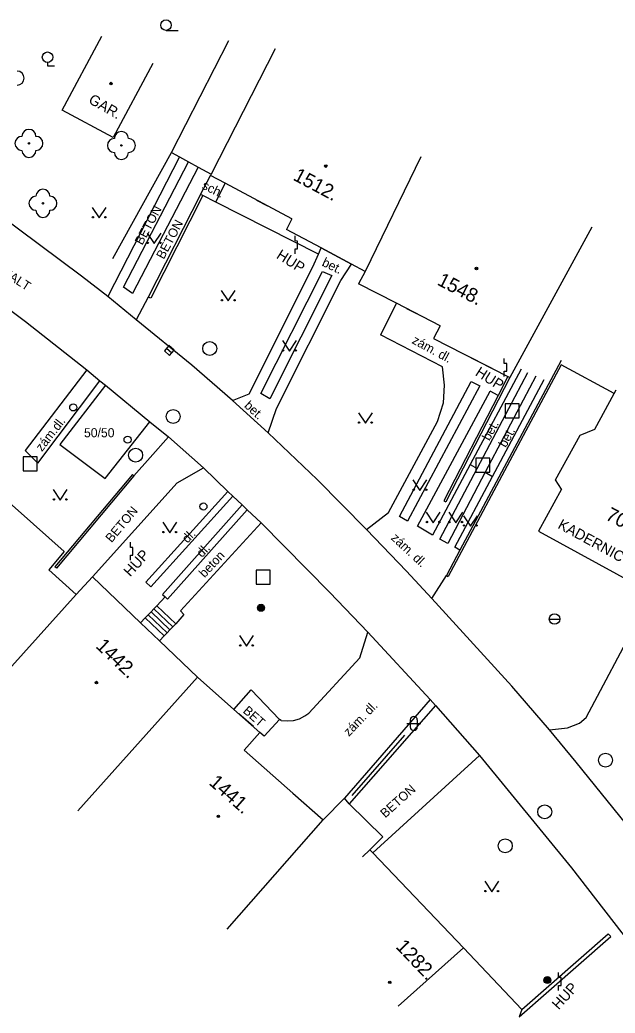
# Model space of a CAD drawing. Extents: x -539244 to -537359, y -1183785 to -1181851.
# Drawn here: x -538380.2 to -538337.7, y -1183558.8 to -1183487.9 of the extents above; entities that cross this region are included whole.
import ezdxf

# ---------------------------------------------------------------- set-up
doc = ezdxf.new("R2010")
doc.units = 0
for name, color, linetype in [('Vrstva 10', 7, 'Continuous'), ('Vrstva 11', 7, 'Continuous'), ('Vrstva 22', 7, 'Continuous'), ('Vrstva 24', 7, 'Continuous'), ('Vrstva 25', 7, 'Continuous'), ('Vrstva 26', 7, 'Continuous'), ('Vrstva 27', 7, 'Continuous'), ('Vrstva 28', 7, 'Continuous'), ('Vrstva 35', 7, 'Continuous'), ('Vrstva 36', 7, 'Continuous'), ('Vrstva 39', 7, 'Continuous'), ('Vrstva 40', 7, 'Continuous'), ('Vrstva 41', 7, 'Continuous'), ('Vrstva 47', 7, 'Continuous'), ('Vrstva 5', 7, 'Continuous'), ('Vrstva 6', 7, 'Continuous'), ('Vrstva 7', 7, 'Continuous'), ('Vrstva 8', 7, 'Continuous')]:
    doc.layers.add(name, color=color, linetype=linetype)

msp = doc.modelspace()

# ---------------------------------------------------------------- linework, layer by layer
at = {"layer": 'Vrstva 10'}
for p, q in [((-538375.8, -1183506.19), (-538382.31, -1183501.34)), ((-538386.84, -1183504.18), (-538379.8, -1183509.42)), ((-538373.93, -1183507.63), (-538375.8, -1183506.19)), ((-538371.9, -1183509.3), (-538373.93, -1183507.63)), ((-538379.8, -1183509.42), (-538375.43, -1183512.88)), ((-538367.92, -1183512.54), (-538371.9, -1183509.3)), ((-538365.03, -1183515.06), (-538367.92, -1183512.54)), ((-538362.48, -1183517.38), (-538365.03, -1183515.06)), ((-538369.59, -1183517.66), (-538367.09, -1183519.86)), ((-538358.99, -1183520.71), (-538362.48, -1183517.38)), ((-538367.09, -1183519.86), (-538365.35, -1183521.57)), ((-538355.45, -1183524.28), (-538358.99, -1183520.71)), ((-538363.98, -1183522.86), (-538362.99, -1183523.8)), ((-538362.99, -1183523.8), (-538358.07, -1183528.76)), ((-538358.07, -1183528.76), (-538355.35, -1183531.61)), ((-538345.09, -1183535.45), (-538350.78, -1183529.2)), ((-538355.35, -1183531.61), (-538350.9, -1183536.41)), ((-538347.39, -1183540.41), (-538340.82, -1183548.43)), ((-538336.46, -1183545.86), (-538340.48, -1183540.88)), ((-538340.82, -1183548.43), (-538334.06, -1183557.17))]:
    msp.add_line(p, q, dxfattribs=at)
for points in [[(-538375.43, -1183512.88), (-538374.49, -1183513.65), (-538374.1, -1183513.98), (-538370.92, -1183516.59), (-538369.59, -1183517.66)], [(-538365.35, -1183521.57), (-538364.99, -1183521.9), (-538364.34, -1183522.52), (-538363.98, -1183522.86)], [(-538350.78, -1183529.2), (-538352.59, -1183527.24), (-538355.45, -1183524.28)], [(-538340.48, -1183540.88), (-538342.38, -1183538.58), (-538345.09, -1183535.45)], [(-538350.9, -1183536.41), (-538350.52, -1183536.83), (-538347.39, -1183540.41)]]:
    msp.add_lwpolyline(points, dxfattribs=at)
at = {"layer": 'Vrstva 11'}
for p, q in [((-538368.8, -1183497.68), (-538373.93, -1183507.63)), ((-538373.58, -1183504.94), (-538369.37, -1183497.36)), ((-538372.82, -1183506.98), (-538368.17, -1183498.03)), ((-538367.47, -1183498.41), (-538372.16, -1183507.43)), ((-538367.32, -1183500.36), (-538366.6, -1183499.01)), ((-538366.223, -1183500.906), (-538365.56, -1183499.56)), ((-538358.88, -1183504.63), (-538358.69, -1183504.17)), ((-538359.29, -1183505.52), (-538358.88, -1183504.63)), ((-538363.84, -1183514.59), (-538359.29, -1183505.52)), ((-538357.3, -1183506.51), (-538356.53, -1183505.33)), ((-538363.01, -1183514.57), (-538358.59, -1183505.86)), ((-538357.94, -1183506.15), (-538362.36, -1183514.95)), ((-538358.59, -1183505.86), (-538357.94, -1183506.15)), ((-538372.16, -1183507.43), (-538372.82, -1183506.98)), ((-538361.88, -1183515.64), (-538357.3, -1183506.51)), ((-538371.04, -1183507.68), (-538371.9, -1183509.3)), ((-538353.306, -1183508.127), (-538354.46, -1183510.37)), ((-538350.02, -1183512.65), (-538354.46, -1183510.37)), ((-538375.43, -1183512.88), (-538379.83, -1183518.63)), ((-538344.42, -1183512.83), (-538348.06, -1183519.64)), ((-538347.55, -1183519.92), (-538343.932, -1183513.077)), ((-538343.361, -1183513.329), (-538346.98, -1183520.19)), ((-538378.93, -1183519.54), (-538374.49, -1183513.65)), ((-538374.1, -1183513.98), (-538377.36, -1183518.2)), ((-538353.11, -1183523.35), (-538347.98, -1183513.7)), ((-538347.37, -1183514.02), (-538352.52, -1183523.67)), ((-538347.98, -1183513.7), (-538347.37, -1183514.02)), ((-538346.46, -1183520.48), (-538342.78, -1183513.56)), ((-538365.03, -1183515.06), (-538363.84, -1183514.59)), ((-538362.36, -1183514.95), (-538363.01, -1183514.57)), ((-538351.81, -1183524.04), (-538346.62, -1183514.4)), ((-538346.052, -1183514.696), (-538346.62, -1183514.4)), ((-538362.48, -1183517.38), (-538361.88, -1183515.64)), ((-538374.13, -1183520.62), (-538370.92, -1183516.59)), ((-538353.89, -1183523.05), (-538350.39, -1183516.56)), ((-538370.9, -1183519.13), (-538369.59, -1183517.66)), ((-538377.36, -1183518.2), (-538374.13, -1183520.62)), ((-538379.83, -1183518.63), (-538378.93, -1183519.54)), ((-538370.9, -1183519.13), (-538372.06, -1183520.45)), ((-538368.97, -1183520.94), (-538367.09, -1183519.86)), ((-538348.06, -1183519.64), (-538350.75, -1183524.67)), ((-538348.06, -1183519.64), (-538347.55, -1183519.92)), ((-538350.22, -1183524.97), (-538347.55, -1183519.92)), ((-538346.98, -1183520.19), (-538349.66, -1183525.27)), ((-538349.15, -1183525.54), (-538346.46, -1183520.48)), ((-538346.98, -1183520.19), (-538346.46, -1183520.48)), ((-538368.97, -1183520.94), (-538375.03, -1183527.64)), ((-538371.22, -1183528.04), (-538365.35, -1183521.57)), ((-538364.99, -1183521.9), (-538370.86, -1183528.37)), ((-538364.34, -1183522.52), (-538370.02, -1183528.9)), ((-538369.66, -1183529.24), (-538363.98, -1183522.86)), ((-538355.45, -1183524.28), (-538353.89, -1183523.05)), ((-538352.52, -1183523.67), (-538353.11, -1183523.35)), ((-538362.99, -1183523.8), (-538368.75, -1183530.08)), ((-538350.75, -1183524.67), (-538351.81, -1183524.04)), ((-538349.66, -1183525.27), (-538350.22, -1183524.97)), ((-538348.79, -1183525.75), (-538349.15, -1183525.54)), ((-538350.78, -1183529.2), (-538349.75, -1183527.56)), ((-538370.86, -1183528.37), (-538371.22, -1183528.04)), ((-538370.02, -1183528.9), (-538369.83, -1183529.08)), ((-538339.78, -1183537.7), (-538335.07, -1183528.82)), ((-538370.43, -1183529.71), (-538369.08, -1183531)), ((-538371.052, -1183530.358), (-538369.702, -1183531.65)), ((-538370.844, -1183530.141), (-538369.494, -1183531.433)), ((-538370.637, -1183529.924), (-538369.287, -1183531.216)), ((-538371.259, -1183530.574), (-538369.909, -1183531.866)), ((-538355.94, -1183533.43), (-538355.35, -1183531.61)), ((-538359.57, -1183537.37), (-538355.94, -1183533.43)), ((-538364.928, -1183537.113), (-538363.7, -1183535.72)), ((-538350.9, -1183536.41), (-538357.03, -1183543.45)), ((-538350.52, -1183536.83), (-538356.7, -1183543.86)), ((-538361.67, -1183537.83), (-538362.77, -1183539.015)), ((-538362.77, -1183539.015), (-538363.07, -1183538.75)), ((-538347.39, -1183540.41), (-538355.013, -1183547.347))]:
    msp.add_line(p, q, dxfattribs=at)
for points in [[(-538358.88, -1183504.63), (-538366.223, -1183500.906), (-538367.137, -1183500.442), (-538367.32, -1183500.36)], [(-538350.39, -1183516.56), (-538349.96, -1183515.23), (-538349.88, -1183513.98), (-538350.02, -1183512.65)], [(-538370.43, -1183529.71), (-538369.83, -1183529.08), (-538369.66, -1183529.24)], [(-538371.597, -1183530.927), (-538371.259, -1183530.574), (-538371.052, -1183530.358), (-538370.844, -1183530.141), (-538370.637, -1183529.924), (-538370.43, -1183529.71)], [(-538368.75, -1183530.08), (-538368.5, -1183530.34), (-538369.08, -1183531)], [(-538370.247, -1183532.219), (-538369.909, -1183531.866), (-538369.702, -1183531.65), (-538369.494, -1183531.433), (-538369.287, -1183531.216), (-538369.08, -1183531)], [(-538361.54, -1183537.9), (-538361.67, -1183537.83), (-538363.7, -1183535.72)], [(-538361.54, -1183537.9), (-538361.105, -1183537.938), (-538360.671, -1183537.896), (-538360.251, -1183537.776), (-538359.86, -1183537.581), (-538359.57, -1183537.37)], [(-538342.38, -1183538.58), (-538341.11, -1183538.43), (-538340.24, -1183538.09), (-538339.78, -1183537.7)]]:
    msp.add_lwpolyline(points, dxfattribs=at)
at = {"layer": 'Vrstva 22'}
for centre in [(-538379.56, -1183496.71), (-538372.96, -1183496.86), (-538378.56, -1183500.99)]:
    msp.add_circle(centre, 0.05, dxfattribs=at)
for centre, start, end in [((-538380.4, -1183492.05), 270, 90), ((-538379.56, -1183496.21), 0, 180), ((-538380.06, -1183496.71), 90, 270), ((-538379.06, -1183496.71), 270, 90), ((-538373.46, -1183496.86), 90, 270), ((-538372.96, -1183496.36), 0, 180), ((-538372.46, -1183496.86), 270, 90), ((-538379.56, -1183497.21), 180, 0), ((-538372.96, -1183497.36), 180, 0), ((-538378.56, -1183500.49), 0, 180), ((-538379.06, -1183500.99), 90, 270), ((-538378.06, -1183500.99), 270, 90), ((-538378.56, -1183501.49), 180, 0)]:
    msp.add_arc(centre, 0.5, start, end, dxfattribs=at)
at = {"layer": 'Vrstva 24'}
for p, q in [((-538360.559, -1183503.679), (-538360.56, -1183503.311)), ((-538360.56, -1183504.6), (-538360.559, -1183504.232)), ((-538360.376, -1183503.68), (-538360.559, -1183503.679)), ((-538360.559, -1183504.232), (-538360.376, -1183504.232)), ((-538360.376, -1183504.232), (-538360.376, -1183503.68)), ((-538345.619, -1183512.429), (-538345.62, -1183512.061)), ((-538345.436, -1183512.43), (-538345.619, -1183512.429)), ((-538345.436, -1183512.982), (-538345.436, -1183512.43)), ((-538345.62, -1183513.35), (-538345.619, -1183512.982)), ((-538345.619, -1183512.982), (-538345.436, -1183512.982)), ((-538372.319, -1183525.549), (-538372.32, -1183525.181)), ((-538372.136, -1183525.55), (-538372.319, -1183525.549)), ((-538372.136, -1183526.102), (-538372.136, -1183525.55)), ((-538372.32, -1183526.47), (-538372.319, -1183526.102)), ((-538372.319, -1183526.102), (-538372.136, -1183526.102)), ((-538341.739, -1183556.259), (-538341.74, -1183555.891)), ((-538341.556, -1183556.26), (-538341.739, -1183556.259)), ((-538341.556, -1183556.812), (-538341.556, -1183556.26)), ((-538341.74, -1183557.18), (-538341.739, -1183556.812)), ((-538341.739, -1183556.812), (-538341.556, -1183556.812))]:
    msp.add_line(p, q, dxfattribs=at)
at = {"layer": 'Vrstva 25'}
for centre, radius in [((-538362.99, -1183529.86), 0.25), ((-538362.99, -1183529.86), 0.2), ((-538362.99, -1183529.86), 0.15), ((-538362.99, -1183529.86), 0.1), ((-538362.99, -1183529.86), 0.05), ((-538342.54, -1183556.43), 0.25), ((-538342.54, -1183556.43), 0.2), ((-538342.54, -1183556.43), 0.15), ((-538342.54, -1183556.43), 0.1), ((-538342.54, -1183556.43), 0.05)]:
    msp.add_circle(centre, radius, dxfattribs=at)
at = {"layer": 'Vrstva 26'}
for points in [[(-538345.56, -1183516.29), (-538344.56, -1183516.29), (-538344.56, -1183515.29), (-538345.56, -1183515.29)], [(-538379.98, -1183520.09), (-538378.98, -1183520.09), (-538378.98, -1183519.09), (-538379.98, -1183519.09)], [(-538347.64, -1183520.17), (-538346.64, -1183520.17), (-538346.64, -1183519.17), (-538347.64, -1183519.17)], [(-538363.33, -1183528.18), (-538362.33, -1183528.18), (-538362.33, -1183527.18), (-538363.33, -1183527.18)]]:
    msp.add_lwpolyline(points, close=True, dxfattribs=at)
at = {"layer": 'Vrstva 27'}
msp.add_line((-538369.728, -1183511.335), (-538369.352, -1183511.665), dxfattribs=at)
msp.add_lwpolyline([(-538369.893, -1183511.522), (-538369.518, -1183511.853), (-538369.187, -1183511.478), (-538369.562, -1183511.147)], close=True, dxfattribs=at)
for centre in [(-538366.655, -1183511.352), (-538369.264, -1183516.203), (-538371.943, -1183518.965), (-538338.387, -1183540.737), (-538342.731, -1183544.425), (-538345.55, -1183546.848)]:
    msp.add_circle(centre, 0.5, dxfattribs=at)
at = {"layer": 'Vrstva 28'}
for centre in [(-538376.4, -1183515.56), (-538372.52, -1183517.86), (-538367.1, -1183522.63)]:
    msp.add_circle(centre, 0.25, dxfattribs=at)
at = {"layer": 'Vrstva 35'}
msp.add_line((-538342.405, -1183530.66), (-538341.655, -1183530.66), dxfattribs=at)
msp.add_circle((-538342.03, -1183530.66), 0.375, dxfattribs=at)
at = {"layer": 'Vrstva 36'}
for p, q in [((-538369.773, -1183488.645), (-538368.898, -1183488.645)), ((-538352.58, -1183538.117), (-538351.58, -1183538.117)), ((-538352.33, -1183537.867), (-538352.33, -1183538.367)), ((-538351.83, -1183537.867), (-538351.83, -1183538.367))]:
    msp.add_line(p, q, dxfattribs=at)
for points in [[(-538378.233, -1183490.937), (-538378.233, -1183491.187), (-538377.733, -1183491.187)], [(-538375.047, -1183501.281), (-538374.547, -1183502.031), (-538374.047, -1183501.281)], [(-538371.126, -1183503.118), (-538370.626, -1183503.868), (-538370.126, -1183503.118)], [(-538365.831, -1183507.209), (-538365.331, -1183507.959), (-538364.831, -1183507.209)], [(-538361.458, -1183510.79), (-538360.958, -1183511.54), (-538360.458, -1183510.79)], [(-538356.038, -1183515.935), (-538355.538, -1183516.685), (-538355.038, -1183515.935)], [(-538352.139, -1183520.733), (-538351.639, -1183521.483), (-538351.139, -1183520.733)], [(-538377.831, -1183521.426), (-538377.331, -1183522.176), (-538376.831, -1183521.426)], [(-538351.194, -1183523.038), (-538350.694, -1183523.788), (-538350.194, -1183523.038)], [(-538349.586, -1183523.038), (-538349.086, -1183523.788), (-538348.586, -1183523.038)], [(-538348.542, -1183523.286), (-538348.042, -1183524.036), (-538347.542, -1183523.286)], [(-538370.004, -1183523.758), (-538369.504, -1183524.508), (-538369.004, -1183523.758)], [(-538364.523, -1183531.848), (-538364.023, -1183532.598), (-538363.523, -1183531.848)], [(-538347.014, -1183549.382), (-538346.514, -1183550.132), (-538346.014, -1183549.382)]]:
    msp.add_lwpolyline(points, dxfattribs=at)
for centre, radius in [((-538369.773, -1183488.27), 0.375), ((-538378.233, -1183490.562), 0.375), ((-538374.997, -1183501.981), 0.05), ((-538374.098, -1183501.981), 0.05), ((-538371.076, -1183503.818), 0.05), ((-538370.177, -1183503.818), 0.05), ((-538365.781, -1183507.909), 0.05), ((-538364.882, -1183507.909), 0.05), ((-538361.408, -1183511.49), 0.05), ((-538360.509, -1183511.49), 0.05), ((-538355.988, -1183516.635), 0.05), ((-538355.089, -1183516.635), 0.05), ((-538352.089, -1183521.433), 0.05), ((-538351.19, -1183521.433), 0.05), ((-538377.781, -1183522.126), 0.05), ((-538376.882, -1183522.126), 0.05), ((-538351.144, -1183523.738), 0.05), ((-538350.245, -1183523.738), 0.05), ((-538349.536, -1183523.738), 0.05), ((-538348.637, -1183523.738), 0.05), ((-538348.492, -1183523.986), 0.05), ((-538347.593, -1183523.986), 0.05), ((-538369.954, -1183524.458), 0.05), ((-538369.055, -1183524.458), 0.05), ((-538364.473, -1183532.548), 0.05), ((-538363.574, -1183532.548), 0.05), ((-538346.964, -1183550.082), 0.05), ((-538346.065, -1183550.082), 0.05)]:
    msp.add_circle(centre, radius, dxfattribs=at)
for centre, start, end in [((-538352.08, -1183537.867), 0, 180), ((-538352.08, -1183538.367), 180, 0)]:
    msp.add_arc(centre, 0.25, start, end, dxfattribs=at)
at = {"layer": 'Vrstva 39'}
for centre, radius in [((-538373.703, -1183492.443), 0.09), ((-538373.703, -1183492.443), 0.0398), ((-538358.367, -1183498.332), 0.09), ((-538358.367, -1183498.332), 0.0398), ((-538347.607, -1183505.644), 0.09), ((-538347.607, -1183505.644), 0.0398), ((-538374.742, -1183535.199), 0.09), ((-538374.742, -1183535.199), 0.0398), ((-538366.037, -1183544.747), 0.09), ((-538366.037, -1183544.747), 0.0398), ((-538353.797, -1183556.589), 0.09), ((-538353.797, -1183556.589), 0.0398)]:
    msp.add_circle(centre, radius, dxfattribs=at)
at = {"layer": 'Vrstva 5'}
for p, q in [((-538377.19, -1183494.35), (-538374.363, -1183489.058)), ((-538370.713, -1183491.008), (-538373.54, -1183496.3)), ((-538373.54, -1183496.3), (-538377.19, -1183494.35)), ((-538351.58, -1183497.66), (-538355.55, -1183505.848)), ((-538360.784, -1183502.107), (-538361.18, -1183502.85)), ((-538358.69, -1183504.17), (-538361.18, -1183502.85)), ((-538339.37, -1183502.68), (-538345.231, -1183513.429)), ((-538355.55, -1183505.848), (-538356.02, -1183506.73)), ((-538353.306, -1183508.127), (-538356.02, -1183506.73)), ((-538350.203, -1183509.723), (-538353.306, -1183508.127)), ((-538350.203, -1183509.723), (-538350.67, -1183510.63)), ((-538339.16, -1183517.1), (-538337.763, -1183514.574)), ((-538337.763, -1183514.574), (-538337.62, -1183514.31)), ((-538341.96, -1183520.73), (-538340.2, -1183517.54)), ((-538340.2, -1183517.54), (-538339.16, -1183517.1)), ((-538341.53, -1183521.4), (-538341.96, -1183520.73)), ((-538341.53, -1183521.4), (-538343.18, -1183524.4)), ((-538343.18, -1183524.4), (-538335.07, -1183528.82)), ((-538375.03, -1183527.64), (-538371.597, -1183530.927)), ((-538370.247, -1183532.219), (-538367.53, -1183534.82)), ((-538376.07, -1183544.36), (-538367.53, -1183534.82)), ((-538367.53, -1183534.82), (-538364.928, -1183537.113)), ((-538364.928, -1183537.113), (-538363.07, -1183538.75)), ((-538364.194, -1183540.025), (-538363.07, -1183538.75)), ((-538364.194, -1183540.025), (-538360.717, -1183543.09)), ((-538360.717, -1183543.09), (-538358.55, -1183545)), ((-538365.415, -1183552.789), (-538358.55, -1183545)), ((-538355.75, -1183547.64), (-538355.22, -1183547.13)), ((-538355.22, -1183547.13), (-538355.013, -1183547.347)), ((-538353.188, -1183558.305), (-538348.542, -1183554.14)), ((-538344.36, -1183558.53), (-538344.55, -1183559.05))]:
    msp.add_line(p, q, dxfattribs=at)
for points in [[(-538361.98, -1183489.96), (-538366.56, -1183498.92), (-538366.6, -1183499.01)], [(-538360.784, -1183502.107), (-538365.56, -1183499.56), (-538366.6, -1183499.01)], [(-538355.55, -1183505.848), (-538356.53, -1183505.33), (-538358.69, -1183504.17)], [(-538350.67, -1183510.63), (-538345.364, -1183513.36), (-538345.231, -1183513.429)], [(-538384.57, -1183538.21), (-538376.18, -1183528.92), (-538375.03, -1183527.64)], [(-538355.013, -1183547.347), (-538348.542, -1183554.14), (-538344.36, -1183558.53)]]:
    msp.add_lwpolyline(points, dxfattribs=at)
at = {"layer": 'Vrstva 6'}
for p, q in [((-538363.32, -1183500.76), (-538362.52, -1183501.18)), ((-538358.69, -1183504.17), (-538356.53, -1183505.33)), ((-538352.59, -1183508.5), (-538351.84, -1183508.88)), ((-538348.01, -1183512), (-538345.97, -1183513.05)), ((-538370.247, -1183532.219), (-538371.597, -1183530.927)), ((-538363.52, -1183538.34), (-538364.57, -1183537.44))]:
    msp.add_line(p, q, dxfattribs=at)
at = {"layer": 'Vrstva 7'}
for p, q in [((-538369.37, -1183497.36), (-538365.29, -1183489.36)), ((-538367.32, -1183500.36), (-538371.04, -1183507.68)), ((-538367.137, -1183500.442), (-538370.862, -1183507.771)), ((-538370.862, -1183507.771), (-538371.04, -1183507.68)), ((-538341.559, -1183512.207), (-538348.79, -1183525.75)), ((-538345.231, -1183513.429), (-538349.79, -1183522.29)), ((-538345.364, -1183513.36), (-538346.052, -1183514.696)), ((-538346.052, -1183514.696), (-538349.923, -1183522.221)), ((-538372.175, -1183520.354), (-538377.711, -1183526.935)), ((-538372.175, -1183520.354), (-538372.06, -1183520.45)), ((-538349.923, -1183522.221), (-538349.79, -1183522.29)), ((-538377.049, -1183525.838), (-538378.14, -1183527.15)), ((-538348.79, -1183525.75), (-538349.75, -1183527.56)), ((-538349.75, -1183527.56), (-538349.617, -1183527.631)), ((-538356.47, -1183543.27), (-538352.72, -1183538.95)), ((-538358.55, -1183545), (-538357.03, -1183543.45)), ((-538354.28, -1183546.22), (-538355.22, -1183547.13)), ((-538344.36, -1183558.53), (-538338.19, -1183553.133)), ((-538338.19, -1183553.133), (-538338.015, -1183553.333)), ((-538342.43, -1183557.195), (-538338.015, -1183553.333)), ((-538344.55, -1183559.05), (-538342.43, -1183557.195))]:
    msp.add_line(p, q, dxfattribs=at)
for points in [[(-538341.55, -1183512.508), (-538344.258, -1183517.58), (-538349.617, -1183527.631)], [(-538372.06, -1183520.45), (-538377.596, -1183527.031), (-538377.711, -1183526.935)]]:
    msp.add_lwpolyline(points, dxfattribs=at)
at = {"layer": 'Vrstva 8'}
for p, q in [((-538337.763, -1183514.574), (-538341.55, -1183512.508)), ((-538376.18, -1183528.92), (-538378.14, -1183527.15))]:
    msp.add_line(p, q, dxfattribs=at)
for points in [[(-538369.37, -1183497.36), (-538368.8, -1183497.68), (-538368.17, -1183498.03), (-538367.47, -1183498.41), (-538366.56, -1183498.92)], [(-538377.049, -1183525.838), (-538380.34, -1183522.92), (-538382.24, -1183521.25)], [(-538354.28, -1183546.22), (-538356.7, -1183543.86), (-538357.03, -1183543.45)]]:
    msp.add_lwpolyline(points, dxfattribs=at)

# ---------------------------------------------------------------- texts
at = {"layer": 'Vrstva 40'}
for s, rotation, p in [('sch.', 333.73155, (-538367.262, -1183499.92)), ('BETON', 61.89825, (-538371.471, -1183504.018)), ('BETON', 61.89825, (-538369.936, -1183505.029)), ('bet.', 334.32436, (-538358.692, -1183505.42)), ('ASFALT', 327.44335, (-538382.469, -1183505.492)), ('zám. dl.', 331.51957, (-538352.262, -1183510.952)), ('bet.', 317.58423, (-538364.234, -1183515.498)), ('zám.dl.', 52.02891, (-538378.636, -1183518.752)), ('bet.', 61.3279, (-538346.677, -1183517.985)), ('bet.', 61.3279, (-538345.503, -1183518.474)), ('BETON', 49.93243, (-538373.662, -1183525.253)), ('dl.', 46.53396, (-538368.239, -1183525.288)), ('zám. dl.', 316.93681, (-538353.751, -1183524.936)), ('dl.', 46.53396, (-538367.208, -1183526.311)), ('beton', 46.79815, (-538367.019, -1183527.756)), ('BET', 318.61459, (-538364.328, -1183537.291)), ('zám. dl.', 46.13319, (-538356.71, -1183539.082)), ('BETON', 41.93224, (-538354.117, -1183544.897))]:
    msp.add_text(s, height=0.65, rotation=rotation, dxfattribs=at).set_placement(p)
msp.add_text('50/50', height=0.65, dxfattribs=at).set_placement((-538375.629, -1183517.689))
at = {"layer": 'Vrstva 41'}
for s, rotation, p in [('GAR.', 330.07601, (-538375.366, -1183493.791)), ('HUP', 327.62347, (-538361.95, -1183504.867)), ('HUP', 327.62347, (-538347.748, -1183513.233)), ('KADERNICTVÍ', 331.36601, (-538341.857, -1183524.145)), ('HUP', 47.67714, (-538372.328, -1183527.695)), ('HUP', 47.67714, (-538341.737, -1183558.596))]:
    msp.add_text(s, height=0.75, rotation=rotation, dxfattribs=at).set_placement(p)
at = {"layer": 'Vrstva 47'}
for s, rotation, p in [('1512.', 331.96485, (-538360.763, -1183499.286)), ('1548.', 332.77298, (-538350.473, -1183506.773)), ('703', 332.47362, (-538338.46, -1183523.518)), ('1442.', 316.24875, (-538374.849, -1183532.659)), ('1441.', 318.60489, (-538366.765, -1183542.425)), ('1282.', 313.61035, (-538353.421, -1183554.093))]:
    msp.add_text(s, height=1, rotation=rotation, dxfattribs=at).set_placement(p)

doc.saveas('drawing.dxf')
